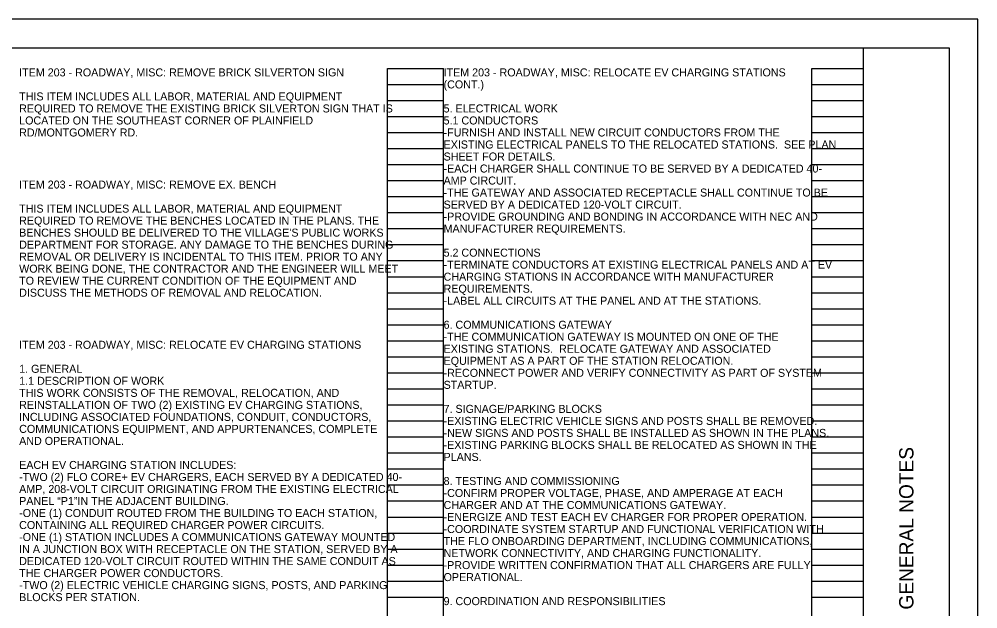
# Model space of a CAD drawing. Extents: x -9.6 to 49.4, y 0 to 27.9.
# Drawn here: x 17.24 to 34, y 11.7 to 22 of the extents above; entities that cross this region are included whole.
import ezdxf

# ---------------------------------------------------------------- set-up
doc = ezdxf.new("R2010")
doc.units = 0
for name, color, linetype in [('SH_Border', 7, 'Continuous'), ('SH_Cut_Line', 7, 'Continuous'), ('SH_Data', 7, 'Continuous'), ('SH_Text', 7, 'Continuous')]:
    doc.layers.add(name, color=color, linetype=linetype)

msp = doc.modelspace()

# ---------------------------------------------------------------- linework, layer by layer
at = {"layer": 'SH_Border'}
msp.add_line((32, 0.5), (32, 21.5), dxfattribs=at)
msp.add_lwpolyline([(1.5, 21.5), (33.5, 21.5), (33.5, 0.5), (1.5, 0.5)], close=True, dxfattribs=at)
at = {"layer": 'SH_Cut_Line'}
msp.add_lwpolyline([(0, 0), (34, 0), (34, 22), (0, 22)], close=True, dxfattribs=at)
at = {"layer": 'SH_Data'}
for p, q in [((23.68, 0.98), (23.68, 21.14)), ((23.68, 21.14), (24.66, 21.14)), ((24.66, 0.98), (24.66, 21.14)), ((31.1, 0.98), (31.1, 21.14)), ((31.1, 21.14), (32, 21.14)), ((32, 0.98), (32, 21.14)), ((23.68, 20.86), (24.66, 20.86)), ((31.1, 20.86), (32, 20.86)), ((23.68, 20.58), (24.66, 20.58)), ((31.1, 20.58), (32, 20.58)), ((23.68, 20.3), (24.66, 20.3)), ((31.1, 20.3), (32, 20.3)), ((23.68, 20.02), (24.66, 20.02)), ((31.1, 20.02), (32, 20.02)), ((23.68, 19.74), (24.66, 19.74)), ((31.1, 19.74), (32, 19.74)), ((23.68, 19.46), (24.66, 19.46)), ((31.1, 19.46), (32, 19.46)), ((23.68, 19.18), (24.66, 19.18)), ((31.1, 19.18), (32, 19.18)), ((23.68, 18.9), (24.66, 18.9)), ((31.1, 18.9), (32, 18.9)), ((23.68, 18.62), (24.66, 18.62)), ((31.1, 18.62), (32, 18.62)), ((23.68, 18.34), (24.66, 18.34)), ((31.1, 18.34), (32, 18.34)), ((23.68, 18.06), (24.66, 18.06)), ((31.1, 18.06), (32, 18.06)), ((23.68, 17.78), (24.66, 17.78)), ((31.1, 17.78), (32, 17.78)), ((23.68, 17.5), (24.66, 17.5)), ((31.1, 17.5), (32, 17.5)), ((23.68, 17.22), (24.66, 17.22)), ((31.1, 17.22), (32, 17.22)), ((23.68, 16.94), (24.66, 16.94)), ((31.1, 16.94), (32, 16.94)), ((23.68, 16.66), (24.66, 16.66)), ((31.1, 16.66), (32, 16.66)), ((23.68, 16.38), (24.66, 16.38)), ((31.1, 16.38), (32, 16.38)), ((23.68, 16.1), (24.66, 16.1)), ((31.1, 16.1), (32, 16.1)), ((23.68, 15.82), (24.66, 15.82)), ((31.1, 15.82), (32, 15.82)), ((23.68, 15.54), (24.66, 15.54)), ((31.1, 15.54), (32, 15.54)), ((23.68, 15.26), (24.66, 15.26)), ((31.1, 15.26), (32, 15.26)), ((23.68, 14.98), (24.66, 14.98)), ((31.1, 14.98), (32, 14.98)), ((23.68, 14.7), (24.66, 14.7)), ((31.1, 14.7), (32, 14.7)), ((23.68, 14.42), (24.66, 14.42)), ((31.1, 14.42), (32, 14.42)), ((23.68, 14.14), (24.66, 14.14)), ((31.1, 14.14), (32, 14.14)), ((23.68, 13.86), (24.66, 13.86)), ((31.1, 13.86), (32, 13.86)), ((23.68, 13.58), (24.66, 13.58)), ((31.1, 13.58), (32, 13.58)), ((23.68, 13.3), (24.66, 13.3)), ((31.1, 13.3), (32, 13.3)), ((23.68, 13.02), (24.66, 13.02)), ((31.1, 13.02), (32, 13.02)), ((23.68, 12.74), (24.66, 12.74)), ((31.1, 12.74), (32, 12.74)), ((23.68, 12.46), (24.66, 12.46)), ((31.1, 12.46), (32, 12.46)), ((23.68, 12.18), (24.66, 12.18)), ((31.1, 12.18), (32, 12.18)), ((23.68, 11.9), (24.66, 11.9)), ((31.1, 11.9), (32, 11.9))]:
    msp.add_line(p, q, dxfattribs=at)

# ---------------------------------------------------------------- texts
msp.add_text('GENERAL NOTES', height=0.25, rotation=90, dxfattribs=at).set_placement((32.875, 11.682))
at = {"layer": 'SH_Text'}
for s, p in [('ITEM 203 - ROADWAY, MISC: REMOVE BRICK SILVERTON SIGN', (17.24, 21)), ('ITEM 203 - ROADWAY, MISC: RELOCATE EV CHARGING STATIONS ', (24.66, 21)), ('(CONT.)', (24.66, 20.79)), ('THIS ITEM INCLUDES ALL LABOR, MATERIAL AND EQUIPMENT ', (17.24, 20.58)), ('REQUIRED TO REMOVE THE EXISTING BRICK SILVERTON SIGN THAT IS ', (17.24, 20.37)), ('5. ELECTRICAL WORK', (24.66, 20.37)), ('LOCATED ON THE SOUTHEAST CORNER OF PLAINFIELD ', (17.24, 20.16)), ('5.1 CONDUCTORS', (24.66, 20.16)), ('RD/MONTGOMERY RD. ', (17.24, 19.95)), ('-FURNISH AND INSTALL NEW CIRCUIT CONDUCTORS FROM THE ', (24.66, 19.95)), ('EXISTING ELECTRICAL PANELS TO THE RELOCATED STATIONS.  SEE PLAN ', (24.66, 19.74)), ('SHEET FOR DETAILS.', (24.66, 19.53)), ('-EACH CHARGER SHALL CONTINUE TO BE SERVED BY A DEDICATED 40-', (24.66, 19.32)), ('ITEM 203 - ROADWAY, MISC: REMOVE EX. BENCH', (17.24, 19.04)), ('AMP CIRCUIT.', (24.66, 19.11)), ('-THE GATEWAY AND ASSOCIATED RECEPTACLE SHALL CONTINUE TO BE ', (24.66, 18.9)), ('SERVED BY A DEDICATED 120-VOLT CIRCUIT.', (24.66, 18.69)), ('THIS ITEM INCLUDES ALL LABOR, MATERIAL AND EQUIPMENT ', (17.24, 18.62)), ('-PROVIDE GROUNDING AND BONDING IN ACCORDANCE WITH NEC AND ', (24.66, 18.48)), ('REQUIRED TO REMOVE THE BENCHES LOCATED IN THE PLANS. THE ', (17.24, 18.41)), ("BENCHES SHOULD BE DELIVERED TO THE VILLAGE'S PUBLIC WORKS ", (17.24, 18.2)), ('MANUFACTURER REQUIREMENTS.', (24.66, 18.27)), ('DEPARTMENT FOR STORAGE. ANY DAMAGE TO THE BENCHES DURING ', (17.24, 17.99)), ('5.2 CONNECTIONS', (24.66, 17.85)), ('REMOVAL OR DELIVERY IS INCIDENTAL TO THIS ITEM. PRIOR TO ANY ', (17.24, 17.78)), ('-TERMINATE CONDUCTORS AT EXISTING ELECTRICAL PANELS AND AT EV ', (24.66, 17.64)), ('WORK BEING DONE, THE CONTRACTOR AND THE ENGINEER WILL MEET ', (17.24, 17.57)), ('TO REVIEW THE CURRENT CONDITION OF THE EQUIPMENT AND ', (17.24, 17.36)), ('CHARGING STATIONS IN ACCORDANCE WITH MANUFACTURER ', (24.66, 17.43)), ('DISCUSS THE METHODS OF REMOVAL AND RELOCATION.  ', (17.24, 17.15)), ('REQUIREMENTS.', (24.66, 17.22)), ('-LABEL ALL CIRCUITS AT THE PANEL AND AT THE STATIONS.', (24.66, 17.01)), ('6. COMMUNICATIONS GATEWAY', (24.66, 16.59)), ('-THE COMMUNICATION GATEWAY IS MOUNTED ON ONE OF THE ', (24.66, 16.38)), ('ITEM 203 - ROADWAY, MISC: RELOCATE EV CHARGING STATIONS', (17.24, 16.24)), ('EXISTING STATIONS.  RELOCATE GATEWAY AND ASSOCIATED ', (24.66, 16.17)), ('EQUIPMENT AS A PART OF THE STATION RELOCATION.', (24.66, 15.96)), ('1. GENERAL', (17.24, 15.82)), ('-RECONNECT POWER AND VERIFY CONNECTIVITY AS PART OF SYSTEM ', (24.66, 15.75)), ('1.1 DESCRIPTION OF WORK', (17.24, 15.61)), ('STARTUP.', (24.66, 15.54)), ('THIS WORK CONSISTS OF THE REMOVAL, RELOCATION, AND ', (17.24, 15.4)), ('REINSTALLATION OF TWO (2) EXISTING EV CHARGING STATIONS, ', (17.24, 15.19)), ('7. SIGNAGE/PARKING BLOCKS', (24.66, 15.12)), ('INCLUDING ASSOCIATED FOUNDATIONS, CONDUIT, CONDUCTORS, ', (17.24, 14.98)), ('-EXISTING ELECTRIC VEHICLE SIGNS AND POSTS SHALL BE REMOVED.', (24.66, 14.91)), ('COMMUNICATIONS EQUIPMENT, AND APPURTENANCES, COMPLETE ', (17.24, 14.77)), ('-NEW SIGNS AND POSTS SHALL BE INSTALLED AS SHOWN IN THE PLANS.', (24.66, 14.7)), ('AND OPERATIONAL.', (17.24, 14.56)), ('-EXISTING PARKING BLOCKS SHALL BE RELOCATED AS SHOWN IN THE ', (24.66, 14.49)), ('PLANS.', (24.66, 14.28)), ('EACH EV CHARGING STATION INCLUDES:', (17.24, 14.14)), ('-TWO (2) FLO CORE+ EV CHARGERS, EACH SERVED BY A DEDICATED 40-', (17.24, 13.93)), ('8. TESTING AND COMMISSIONING', (24.66, 13.86)), ('AMP, 208-VOLT CIRCUIT ORIGINATING FROM THE EXISTING ELECTRICAL ', (17.24, 13.72)), ('-CONFIRM PROPER VOLTAGE, PHASE, AND AMPERAGE AT EACH ', (24.66, 13.65)), ('PANEL “P1”IN THE ADJACENT BUILDING.', (17.24, 13.51)), ('CHARGER AND AT THE COMMUNICATIONS GATEWAY.', (24.66, 13.44)), ('-ONE (1) CONDUIT ROUTED FROM THE BUILDING TO EACH STATION, ', (17.24, 13.3)), ('-ENERGIZE AND TEST EACH EV CHARGER FOR PROPER OPERATION.', (24.66, 13.23)), ('CONTAINING ALL REQUIRED CHARGER POWER CIRCUITS.', (17.24, 13.09)), ('-COORDINATE SYSTEM STARTUP AND FUNCTIONAL VERIFICATION WITH ', (24.66, 13.02)), ('-ONE (1) STATION INCLUDES A COMMUNICATIONS GATEWAY MOUNTED ', (17.24, 12.88)), ('THE FLO ONBOARDING DEPARTMENT, INCLUDING COMMUNICATIONS, ', (24.66, 12.81)), ('IN A JUNCTION BOX WITH RECEPTACLE ON THE STATION, SERVED BY A ', (17.24, 12.67)), ('NETWORK CONNECTIVITY, AND CHARGING FUNCTIONALITY.', (24.66, 12.6)), ('DEDICATED 120-VOLT CIRCUIT ROUTED WITHIN THE SAME CONDUIT AS ', (17.24, 12.46)), ('-PROVIDE WRITTEN CONFIRMATION THAT ALL CHARGERS ARE FULLY ', (24.66, 12.39)), ('THE CHARGER POWER CONDUCTORS.', (17.24, 12.25)), ('OPERATIONAL.', (24.66, 12.18)), ('-TWO (2) ELECTRIC VEHICLE CHARGING SIGNS, POSTS, AND PARKING ', (17.24, 12.04)), ('BLOCKS PER STATION.', (17.24, 11.83)), ('9. COORDINATION AND RESPONSIBILITIES', (24.66, 11.76))]:
    msp.add_text(s, height=0.14, dxfattribs=at).set_placement(p)

doc.saveas('drawing.dxf')
